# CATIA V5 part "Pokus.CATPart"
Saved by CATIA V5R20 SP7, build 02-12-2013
Part number: Pokus
Bounding box of the stored display mesh (mm): x -17.5 to 17.5, y -20 to 10, z -7.9 to 0
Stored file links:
  C:\Users\wcz0113\Desktop\Pokus.CATPart
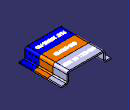
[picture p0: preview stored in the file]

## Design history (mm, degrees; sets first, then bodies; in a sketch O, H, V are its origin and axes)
SheetMetalParameters1: Thickness 1, BendRadius 0.8, KFactor 0.30103 {= log(min(100,max(20*SheetMetalParameters1.BendRadius,SheetMetalParameters1.Thickness)/SheetMetalParameters1.Thickness))/log(100)/2}, ReliefRadialLength 1, ReliefAxialLength 2, WallPerLength 50, MinimumBendRadius 0
AxisSystem1: origin (0, 0, 0), X (1, 0, 0), Y (0, 1, 0), Z (0, 0, 1)
Set1 "Extract"
  Extract1: ExtractElem face of Pad1 from Sketch3.E10
Body1 "Wall on edge" (main body)
  Sketch1 on xy-plane, origin (0, 0, 0), H (1, 0, 0), V (0, 1, 0)
    line L1 (-12.5, 10) -> (12.5, 10)
    line L2 (12.5, 10) -> (12.5, 0)
    line L3 (12.5, 0) -> (-12.5, 0)
    line L4 (-12.5, 0) -> (-12.5, 10)
    reference projected line E1 through (0, 0) direction (1, 0) from edge [XY plane of AxisSystem1 | ZX plane of AxisSystem1]
    reference projected line E2 through (0, 0) direction (0, 1) from edge [YZ plane of AxisSystem1 | XY plane of AxisSystem1]
    distance L1 L3 = 10
    distance L2 L4 = 25
    horizontal: L1 H, L3 H
    vertical: L2 V, L4 V
    coincidence: L3 E1
    symmetry: L2 L4 E2
  Wall1: Thickness 1, Profile Sketch1
  d_NewWallOnEdge1: NewWallOnEdge_Length 6.9, KFacteur 0.30103 {= log(min(100,max(20*d_NewWallOnEdge1.Radius,SheetMetalParameters1.Thickness)/SheetMetalParameters1.Thickness))/log(100)/2}, NewWallOnEdge_HeightLimitOffset 0, NewWallOnEdge_WidthOffset1 0, NewWallOnEdge_WidthOffset2 0, NewWallOnEdge_Angle 90, NewWallOnEdge_BendRadiusValue 0.8 {= SheetMetalParameters1.BendRadius}, NewWallOnEdge_BendTable SheetMetalParameters1, NewWallOnEdge_GapValue 0, NewWallOnEdge_Edge edge [face of Wall1 | face of Wall1]
  d_NewWallOnEdge2: NewWallOnEdge_Length 6.9, NewWallOnEdge_HeightLimitOffset 0, NewWallOnEdge_WidthOffset1 0, NewWallOnEdge_WidthOffset2 0, NewWallOnEdge_Angle 90, NewWallOnEdge_BendRadiusValue 0.8 {= SheetMetalParameters1.BendRadius}, NewWallOnEdge_BendTable SheetMetalParameters1, NewWallOnEdge_GapValue 0, NewWallOnEdge_Edge edge [face of Wall1 | face of Wall1], KFacteur 0.30103 {= log(min(100,max(20*d_NewWallOnEdge2.Radius,SheetMetalParameters1.Thickness)/SheetMetalParameters1.Thickness))/log(100)/2}
  d_NewWallOnEdge3: NewWallOnEdge_Length 5, NewWallOnEdge_HeightLimitOffset 0, NewWallOnEdge_WidthOffset1 0, NewWallOnEdge_WidthOffset2 0, NewWallOnEdge_Angle 90, NewWallOnEdge_BendRadiusValue 0.8 {= SheetMetalParameters1.BendRadius}, NewWallOnEdge_BendTable SheetMetalParameters1, NewWallOnEdge_GapValue 0, NewWallOnEdge_Edge edge [face of d_NewWallOnEdge1 | face of d_NewWallOnEdge1], KFacteur 0.30103 {= log(min(100,max(20*d_NewWallOnEdge3.Radius,SheetMetalParameters1.Thickness)/SheetMetalParameters1.Thickness))/log(100)/2}
  d_NewWallOnEdge4: NewWallOnEdge_Length 5, NewWallOnEdge_HeightLimitOffset 0, NewWallOnEdge_WidthOffset1 0, NewWallOnEdge_WidthOffset2 0, NewWallOnEdge_Angle 90, NewWallOnEdge_BendRadiusValue 0.8 {= SheetMetalParameters1.BendRadius}, NewWallOnEdge_BendTable SheetMetalParameters1, NewWallOnEdge_GapValue 0, NewWallOnEdge_Edge edge [face of d_NewWallOnEdge2 | face of d_NewWallOnEdge2], KFacteur 0.30103 {= log(min(100,max(20*d_NewWallOnEdge4.Radius,SheetMetalParameters1.Thickness)/SheetMetalParameters1.Thickness))/log(100)/2}
  Sketch2 "Main View" on face of Pad1, origin (0, 0, 0), H (1, 0, 0), V (0, 1, 0)
    polyline C1
    polyline C2
    polyline C3
    polyline C4
    polyline C5
    polyline C6
    polyline C7
    polyline C8
    polyline C9
    polyline C10
    polyline C11
    polyline C12
    polyline C13
    polyline C14
    polyline C15
    polyline C16
    polyline C17
    polyline C18
Body2 "Part design"
  Sketch3 on face of Wall1, origin (0, 0, 0), H (1, 0, 0), V (0, 0, 1)
    projected line E1 (-17.5, -6.9) -> (-17.5, -7.9) from edge [face of d_NewWallOnEdge3 | face of d_NewWallOnEdge3]
    projected line E2 (-17.5, -7.9) -> (-14.3, -7.9) from edge [face of d_NewWallOnEdge3 | face of d_NewWallOnEdge3]
    projected line E3 (-17.5, -6.9) -> (-14.3, -6.9) from edge [face of d_NewWallOnEdge3 | face of d_NewWallOnEdge3]
    projected arc E4 centre (-14.3, -6.1) radius 0.8 from (-14.3, -6.9) to (-13.5, -6.1) ccw from edge [face of d_NewWallOnEdge3 | face of d_NewWallOnEdge3]
    projected arc E5 centre (-14.3, -6.1) radius 1.8 from (-14.3, -7.9) to (-12.5, -6.1) ccw from edge [face of d_NewWallOnEdge3 | face of d_NewWallOnEdge3]
    projected line E6 (-12.5, -1.8) -> (-12.5, -6.1) from edge [face of d_NewWallOnEdge1 | face of d_NewWallOnEdge1]
    projected line E7 (-13.5, -6.1) -> (-13.5, -1.8) from edge [face of d_NewWallOnEdge1 | face of d_NewWallOnEdge1]
    projected arc E8 centre (-11.7, -1.8) radius 0.8 from (-11.7, -1) to (-12.5, -1.8) ccw from edge [face of d_NewWallOnEdge1 | face of d_NewWallOnEdge1]
    projected arc E9 centre (-11.7, -1.8) radius 1.8 from (-11.7, 0) to (-13.5, -1.8) ccw from edge [face of d_NewWallOnEdge1 | face of d_NewWallOnEdge1]
    projected line E10 (11.7, 0) -> (-11.7, 0) from edge [face of Wall1 | face of Wall1]
    projected line E11 (11.7, -1) -> (-11.7, -1) from edge [face of Wall1 | face of Wall1]
    projected arc E12 centre (11.7, -1.8) radius 0.8 from (12.5, -1.8) to (11.7, -1) ccw from edge [face of d_NewWallOnEdge2 | face of d_NewWallOnEdge2]
    projected arc E13 centre (11.7, -1.8) radius 1.8 from (13.5, -1.8) to (11.7, 0) ccw from edge [face of d_NewWallOnEdge2 | face of d_NewWallOnEdge2]
    projected line E14 (13.5, -6.1) -> (13.5, -1.8) from edge [face of d_NewWallOnEdge2 | face of d_NewWallOnEdge2]
    projected line E15 (12.5, -1.8) -> (12.5, -6.1) from edge [face of d_NewWallOnEdge2 | face of d_NewWallOnEdge2]
    projected arc E16 centre (14.3, -6.1) radius 1.8 from (12.5, -6.1) to (14.3, -7.9) ccw from edge [face of d_NewWallOnEdge4 | face of d_NewWallOnEdge4]
    projected arc E17 centre (14.3, -6.1) radius 0.8 from (13.5, -6.1) to (14.3, -6.9) ccw from edge [face of d_NewWallOnEdge4 | face of d_NewWallOnEdge4]
    projected line E18 (14.3, -6.9) -> (17.5, -6.9) from edge [face of d_NewWallOnEdge4 | face of d_NewWallOnEdge4]
    projected line E19 (17.5, -6.9) -> (17.5, -7.9) from edge [face of d_NewWallOnEdge4 | face of d_NewWallOnEdge4]
    projected line E20 (14.3, -7.9) -> (17.5, -7.9) from edge [face of d_NewWallOnEdge4 | face of d_NewWallOnEdge4]
  Pad1: profile Sketch3, direction (0, -1, 0), length 10
  Translate1: Direction edge [YZ plane of AxisSystem1 | XY plane of AxisSystem1], ToTransfor Pad1, Length -10
  Sketch4 "Main View" on face of Pad1, origin (0, 0, 0), H (1, 0, 0), V (0, 1, 0)
    polyline C1
    polyline C2
    polyline C3
    polyline C4
    polyline C5
    polyline C6
    polyline C7
    polyline C8
    polyline C9
    polyline C10
    polyline C11
    polyline C12
    polyline C13
    polyline C14
    polyline C15
    polyline C16
    polyline C17
    polyline C18
    polyline C19
    polyline C20
    polyline C21
Body3 "Hooper"
  Hopper1: KFacteur 0.30103 {= SheetMetalParameters1.KFactor}, HopperFixedSideType 0, HopperType 0, Hopper_DeductionTable SheetMetalParameters1, Hopper_NeutralFiber 0, Hopper_Thickness 1, Hopper_InvariantPoint vertex [face of Pad1 from Sketch3.E13 | face of Pad1 from Sketch3.E10], Hopper_ReferenceEdge edge [face of Pad1 from Sketch3.E10 | face of Pad1 from Sketch3.E13], Hopper_Surface Extract1
  Sketch5 "Main View" on face of Pad1, origin (0, 0, 0), H (1, 0, 0), V (0, 1, 0)
    polyline C1
    polyline C2
    polyline C3
    polyline C4
    polyline C5
    polyline C6
    polyline C7
    polyline C8
    polyline C9
    polyline C10
    polyline C11
    polyline C12
    polyline C13
    polyline C14
    polyline C15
